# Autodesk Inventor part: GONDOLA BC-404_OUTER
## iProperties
Shininess: 64.0
Length Units: 11272
Angle Units: 11279
Time Units: 11290
Mass Units: 11286
Length Display Precision: 3
Angle Display Precision: 2
Compacted: True
Part Number: GONDOLA BC-404_OUTER
Document SubType Name: Modeling
Created: 2004-08
Designer: John Blackburn
Manufacturer: Standard
Standards Organization: Custom
Material: Lexan, Clear
Density: 0.0
Volumn: 0.0
Area: 0.0
PropertySet Name: Model Information
Control State: 0
Master: False
Checked Out: False
Author: John Blackburn
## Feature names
1. Base1
